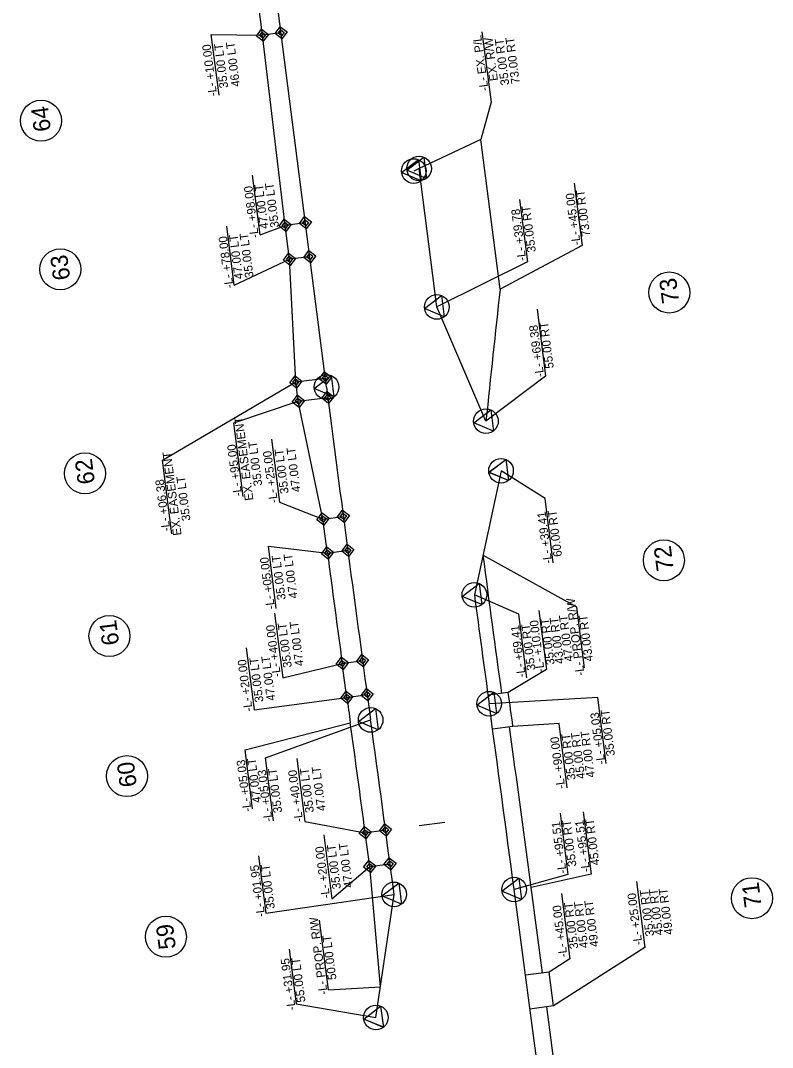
# Model space of a CAD drawing. Extents: x 2368169 to 2369183, y 801414 to 808542.
# Drawn here: x 2368302 to 2368742, y 806520 to 807120 of the extents above; entities that cross this region are included whole.
import ezdxf

# ---------------------------------------------------------------- set-up
doc = ezdxf.new("R2010")
doc.units = 0
for name, color, linetype in [('Prop Easement Construction', 7, 'Continuous'), ('Prop Easement Construction Station Offsets', 7, 'Continuous'), ('Prop Easement Permanent Drainage', 7, 'Continuous'), ('Prop Easement Permanent Drainage Station Offsets', 7, 'Continuous'), ('Prop Easement Permanent Drainage Utility', 7, 'Continuous'), ('Prop Easement Permanent Drainage Utility Station Offsets', 7, 'Continuous'), ('Prop Parcel Number CELL', 7, 'Continuous'), ('Prop Parcel Number Text', 7, 'Continuous'), ('Prop ROW Marker CELL', 7, 'Continuous'), ('Prop ROW Permanent Easement CELL', 7, 'Continuous'), ('Prop ROW RW Lines', 7, 'Continuous'), ('Prop ROW Station Offsets', 7, 'Continuous')]:
    doc.layers.add(name, color=color, linetype=linetype)

msp = doc.modelspace()

# ---------------------------------------------------------------- linework, layer by layer
at = {"layer": 'Prop Easement Construction'}
for p, q in [((2368456.82, 807000.63), (2368443.56, 807111.84)), ((2368463.06, 806909.05), (2368459.36, 806980.79)), ((2368478.97, 806828.89), (2368464.55, 806897.76)), ((2368512.61, 806555.37), (2368506.34, 806625.66)), ((2368607.38, 806563.4), (2368600.76, 806613.48)), ((2368629.17, 806398.45), (2368610, 806543.58))]:
    msp.add_line(p, q, dxfattribs=at)
for centre, radius, start, end in [((2390619.79, 809742.63), 22331.72, 187.54847, 187.715583), ((2391111.53, 809808.52), 22737.85, 187.583666, 187.789219), ((2390193.95, 809683.11), 21901.75, 187.763273, 187.802507), ((2347336.87, 803808.82), 21356.05, 7.63287, 7.806987), ((2345971.56, 803623.74), 22825.85, 7.526261, 7.763901)]:
    msp.add_arc(centre, radius, start, end, dxfattribs=at)
at = {"layer": 'Prop Easement Construction Station Offsets'}
for p, q in [((2368433.36, 806693.96), (2368494.98, 806709.75)), ((2368437.76, 806659.5), (2368433.36, 806693.96)), ((2368482.14, 806553.46), (2368476.92, 806594.32)), ((2368482.14, 806553.46), (2368512.61, 806555.37))]:
    msp.add_line(p, q, dxfattribs=at)
for points in [[(2368631.99, 806741.85), (2368627.46, 806777.36), (2368572.56, 806807.72)], [(2368631.34, 806657.64), (2368635.99, 806621.22), (2368600.76, 806613.48)]]:
    msp.add_lwpolyline(points, dxfattribs=at)
at = {"layer": 'Prop Easement Permanent Drainage'}
for p, q in [((2368571.36, 807050.84), (2368535.23, 807033.87)), ((2368582.58, 806963.32), (2368571.36, 807050.84)), ((2368587.43, 806727.42), (2368575.54, 806725.79)), ((2368590.15, 806707.58), (2368578.26, 806705.96)), ((2368611.34, 806563.93), (2368597.46, 806562.09)), ((2368613.96, 806544.1), (2368611.34, 806563.93)), ((2368613.96, 806544.1), (2368600.08, 806542.27))]:
    msp.add_line(p, q, dxfattribs=at)
for centre, radius, start, end in [((2400172.77, 803560.17), 31772.96, 173.851337, 173.99136), ((2345971.56, 803623.74), 22827.85, 7.763901, 7.814153)]:
    msp.add_arc(centre, radius, start, end, dxfattribs=at)
at = {"layer": 'Prop Easement Permanent Drainage Station Offsets'}
for p, q in [((2368662.43, 806616.97), (2368667.38, 806578.25)), ((2368618.58, 806609.82), (2368623.45, 806571.69)), ((2368667.38, 806578.25), (2368613.96, 806544.1)), ((2368623.45, 806571.69), (2368611.34, 806563.93))]:
    msp.add_line(p, q, dxfattribs=at)
for points in [[(2368571.96, 807113.86), (2368577.41, 807072.68), (2368571.36, 807050.84)], [(2368625.97, 807025.32), (2368630.61, 806988.94), (2368582.58, 806963.32)], [(2368605.39, 806775.37), (2368609.8, 806740.83), (2368587.43, 806727.42)], [(2368621.98, 806671.75), (2368617.17, 806709.37), (2368590.15, 806707.58)]]:
    msp.add_lwpolyline(points, dxfattribs=at)
at = {"layer": 'Prop Easement Permanent Drainage Utility'}
for p, q in [((2368443.56, 807111.84), (2368441.02, 807131.68)), ((2368454.47, 807113.24), (2368443.56, 807111.84)), ((2368468.72, 807002.15), (2368456.82, 807000.63)), ((2368459.36, 806980.79), (2368456.82, 807000.63)), ((2368471.26, 806982.32), (2368459.36, 806980.79)), ((2368463.06, 806909.05), (2368480.37, 806911.33)), ((2368464.55, 806897.76), (2368463.06, 806909.05)), ((2368464.55, 806897.76), (2368481.82, 806899.98)), ((2368478.97, 806828.89), (2368490.87, 806830.46)), ((2368481.6, 806809.02), (2368478.97, 806828.89)), ((2368481.6, 806809.02), (2368493.49, 806810.6)), ((2368490.25, 806744.47), (2368502.14, 806746.08)), ((2368492.95, 806724.61), (2368490.25, 806744.47)), ((2368492.95, 806724.61), (2368504.84, 806726.23)), ((2368503.69, 806645.44), (2368515.59, 806647.03)), ((2368535.32, 806649.68), (2368550.28, 806651.69)), ((2368506.34, 806625.66), (2368503.69, 806645.44)), ((2368506.34, 806625.66), (2368518.23, 806627.24))]:
    msp.add_line(p, q, dxfattribs=at)
at = {"layer": 'Prop Easement Permanent Drainage Utility Station Offsets'}
for p, q in [((2368442.16, 806995.03), (2368437.7, 807029.94)), ((2368427.04, 806965.62), (2368422.64, 807000.07)), ((2368442.16, 806995.03), (2368456.82, 807000.63)), ((2368427.04, 806965.62), (2368459.36, 806980.79)), ((2368384.98, 806863.31), (2368463.06, 806909.05)), ((2368426.73, 806885.17), (2368464.55, 806897.76)), ((2368432.24, 806842.02), (2368426.73, 806885.17)), ((2368390.49, 806820.16), (2368384.98, 806863.31)), ((2368463.6, 806688.93), (2368468.32, 806652.01)), ((2368468.32, 806652.01), (2368503.69, 806645.44))]:
    msp.add_line(p, q, dxfattribs=at)
for points in [[(2368418.15, 807076.8), (2368413.61, 807112.33), (2368443.56, 807111.84)], [(2368448.86, 806875.53), (2368453.55, 806838.79), (2368478.97, 806828.89)], [(2368451.67, 806776.56), (2368447.02, 806812.98), (2368481.6, 806809.02)], [(2368450.68, 806773.78), (2368455.5, 806735.99), (2368490.25, 806744.47)], [(2368434.09, 806753.57), (2368438.72, 806717.27), (2368492.95, 806724.61)], [(2368479.44, 806644.24), (2368484.21, 806606.86), (2368506.34, 806625.66)]]:
    msp.add_lwpolyline(points, dxfattribs=at)
at = {"layer": 'Prop Parcel Number CELL'}
for p, q in [((2368313.96, 807061.81), (2368313.96, 807061.81)), ((2368325.25, 806974.96), (2368325.25, 806974.96)), ((2368681.65, 806961.36), (2368681.65, 806961.36)), ((2368339.69, 806855.59), (2368339.69, 806855.59)), ((2368678.48, 806804.78), (2368678.48, 806804.78)), ((2368354.01, 806760.49), (2368354.01, 806760.49)), ((2368364.24, 806678.53), (2368364.24, 806678.53)), ((2368730.05, 806607.14), (2368730.05, 806607.14)), ((2368387.04, 806584.6), (2368387.04, 806584.6))]:
    msp.add_line(p, q, dxfattribs=at)
for centre in [(2368313.96, 807061.81), (2368325.25, 806974.96), (2368681.65, 806961.36), (2368339.69, 806855.59), (2368678.48, 806804.78), (2368354.01, 806760.49), (2368364.24, 806678.53), (2368730.05, 806607.14), (2368387.04, 806584.6)]:
    msp.add_circle(centre, 12, dxfattribs=at)
at = {"layer": 'Prop ROW Marker CELL'}
for p, q in [((2368532.12, 807032.41), (2368532.12, 807032.41)), ((2368532.12, 807032.41), (2368532.12, 807032.41)), ((2368535.23, 807033.87), (2368535.23, 807033.87)), ((2368535.23, 807033.87), (2368535.23, 807033.87)), ((2368545.61, 806952.91), (2368545.61, 806952.91)), ((2368545.61, 806952.91), (2368545.61, 806952.91)), ((2368481.04, 806906.1), (2368481.04, 806906.1)), ((2368481.04, 806906.1), (2368481.04, 806906.1)), ((2368574.36, 806886.11), (2368574.36, 806886.11)), ((2368574.36, 806886.11), (2368574.36, 806886.11)), ((2368583.18, 806857.11), (2368583.18, 806857.11)), ((2368583.18, 806857.11), (2368583.18, 806857.11)), ((2368567.58, 806784.58), (2368567.58, 806784.58)), ((2368567.58, 806784.58), (2368567.58, 806784.58)), ((2368576.22, 806720.88), (2368576.22, 806720.88)), ((2368576.22, 806720.88), (2368576.22, 806720.88)), ((2368506.87, 806711.38), (2368506.87, 806711.38)), ((2368506.87, 806711.38), (2368506.87, 806711.38)), ((2368590.85, 806612.17), (2368590.85, 806612.17)), ((2368590.85, 806612.17), (2368590.85, 806612.17)), ((2368520.61, 806609.37), (2368520.61, 806609.37)), ((2368520.61, 806609.37), (2368520.61, 806609.37)), ((2368509.95, 806537.37), (2368509.95, 806537.37)), ((2368509.95, 806537.37), (2368509.95, 806537.37))]:
    msp.add_line(p, q, dxfattribs=at)
for points in [[(2368536.49, 807026.67), (2368524.98, 807031.49), (2368534.89, 807039.07)], [(2368536.49, 807026.66), (2368524.98, 807031.5), (2368534.9, 807039.06)], [(2368539.59, 807028.12), (2368528.08, 807032.95), (2368538.01, 807040.52)], [(2368539.6, 807028.13), (2368528.09, 807032.95), (2368538, 807040.52)], [(2368549.98, 806947.18), (2368538.47, 806951.99), (2368548.38, 806959.57)], [(2368549.97, 806947.17), (2368538.47, 806952), (2368548.39, 806959.57)], [(2368485.41, 806900.36), (2368473.9, 806905.18), (2368483.81, 806912.76)], [(2368485.4, 806900.36), (2368473.9, 806905.19), (2368483.82, 806912.76)], [(2368578.73, 806880.37), (2368567.22, 806885.19), (2368577.13, 806892.77)], [(2368578.73, 806880.37), (2368567.22, 806885.2), (2368577.14, 806892.77)], [(2368587.55, 806851.37), (2368576.04, 806856.19), (2368585.96, 806863.77)], [(2368587.55, 806851.37), (2368576.04, 806856.2), (2368585.96, 806863.77)], [(2368571.95, 806778.84), (2368560.44, 806783.66), (2368570.35, 806791.23)], [(2368571.94, 806778.83), (2368560.44, 806783.66), (2368570.36, 806791.23)], [(2368580.59, 806715.14), (2368569.08, 806719.96), (2368578.99, 806727.54)], [(2368580.58, 806715.14), (2368569.08, 806719.97), (2368579, 806727.54)], [(2368511.23, 806705.64), (2368499.72, 806710.46), (2368509.64, 806718.04)], [(2368511.23, 806705.63), (2368499.72, 806710.47), (2368509.64, 806718.03)], [(2368595.21, 806606.43), (2368583.7, 806611.25), (2368593.62, 806618.83)], [(2368595.21, 806606.43), (2368583.7, 806611.26), (2368593.62, 806618.83)], [(2368524.97, 806603.63), (2368513.46, 806608.46), (2368523.39, 806616.03)], [(2368524.98, 806603.64), (2368513.47, 806608.45), (2368523.38, 806616.03)], [(2368514.31, 806531.62), (2368502.8, 806536.46), (2368512.73, 806544.02)], [(2368514.32, 806531.63), (2368502.81, 806536.45), (2368512.72, 806544.03)]]:
    msp.add_lwpolyline(points, close=True, dxfattribs=at)
for centre in [(2368532.12, 807032.41), (2368535.23, 807033.87), (2368545.61, 806952.91), (2368481.04, 806906.1), (2368574.36, 806886.11), (2368583.18, 806857.11), (2368567.58, 806784.58), (2368576.22, 806720.88), (2368506.87, 806711.38), (2368520.61, 806609.37), (2368590.85, 806612.17), (2368509.95, 806537.37)]:
    msp.add_circle(centre, 7.2, dxfattribs=at)
at = {"layer": 'Prop ROW Permanent Easement CELL'}
for p, q in [((2368443.56, 807111.84), (2368443.56, 807111.84)), ((2368454.47, 807113.24), (2368454.47, 807113.24)), ((2368468.72, 807002.15), (2368468.72, 807002.15)), ((2368456.82, 807000.63), (2368456.82, 807000.63)), ((2368459.36, 806980.79), (2368459.36, 806980.79)), ((2368471.26, 806982.32), (2368471.26, 806982.32)), ((2368480.37, 806911.33), (2368480.37, 806911.33)), ((2368463.06, 806909.05), (2368463.06, 806909.05)), ((2368481.82, 806899.98), (2368481.82, 806899.98)), ((2368464.55, 806897.76), (2368464.55, 806897.76)), ((2368478.97, 806828.89), (2368478.97, 806828.89)), ((2368490.87, 806830.46), (2368490.87, 806830.46)), ((2368481.6, 806809.02), (2368481.6, 806809.02)), ((2368493.49, 806810.6), (2368493.49, 806810.6)), ((2368490.25, 806744.47), (2368490.25, 806744.47)), ((2368502.14, 806746.08), (2368502.14, 806746.08)), ((2368492.95, 806724.61), (2368492.95, 806724.61)), ((2368504.84, 806726.23), (2368504.84, 806726.23)), ((2368515.59, 806647.03), (2368515.59, 806647.03)), ((2368503.69, 806645.44), (2368503.69, 806645.44)), ((2368506.34, 806625.66), (2368506.34, 806625.66)), ((2368518.23, 806627.24), (2368518.23, 806627.24))]:
    msp.add_line(p, q, dxfattribs=at)
for points in [[(2368444.03, 807108.28), (2368439.99, 807111.37), (2368443.09, 807115.41), (2368447.13, 807112.32)], [(2368454.95, 807109.68), (2368450.9, 807112.77), (2368454, 807116.81), (2368458.04, 807113.72)], [(2368454.71, 807111.46), (2368452.69, 807113.01), (2368454.24, 807115.03), (2368456.26, 807113.48)], [(2368443.8, 807110.06), (2368441.78, 807111.61), (2368443.33, 807113.63), (2368445.35, 807112.08)], [(2368457.29, 806997.06), (2368453.25, 807000.15), (2368456.35, 807004.2), (2368460.39, 807001.1)], [(2368457.05, 806998.84), (2368455.03, 807000.39), (2368456.58, 807002.41), (2368458.6, 807000.86)], [(2368469.19, 806998.59), (2368465.15, 807001.68), (2368468.25, 807005.72), (2368472.29, 807002.63)], [(2368468.96, 807000.37), (2368466.94, 807001.92), (2368468.48, 807003.94), (2368470.5, 807002.39)], [(2368459.83, 806977.22), (2368455.79, 806980.32), (2368458.89, 806984.36), (2368462.93, 806981.26)], [(2368471.74, 806978.75), (2368467.7, 806981.84), (2368470.79, 806985.88), (2368474.83, 806982.79)], [(2368471.5, 806980.53), (2368469.48, 806982.08), (2368471.03, 806984.1), (2368473.05, 806982.55)], [(2368459.6, 806979.01), (2368457.58, 806980.55), (2368459.13, 806982.57), (2368461.15, 806981.03)], [(2368462.61, 806912.62), (2368466.63, 806909.51), (2368463.52, 806905.48), (2368459.49, 806908.6)], [(2368462.83, 806910.84), (2368464.85, 806909.28), (2368463.29, 806907.27), (2368461.28, 806908.83)], [(2368479.91, 806914.9), (2368483.94, 806911.79), (2368480.82, 806907.76), (2368476.8, 806910.87)], [(2368480.14, 806913.11), (2368482.15, 806911.56), (2368480.6, 806909.54), (2368478.58, 806911.1)], [(2368464.09, 806901.33), (2368468.12, 806898.22), (2368465, 806894.19), (2368460.97, 806897.3)], [(2368464.32, 806899.55), (2368466.33, 806897.99), (2368464.77, 806895.98), (2368462.76, 806897.53)], [(2368481.37, 806903.55), (2368485.4, 806900.44), (2368482.28, 806896.41), (2368478.25, 806899.52)], [(2368481.6, 806901.77), (2368483.61, 806900.21), (2368482.05, 806898.2), (2368480.04, 806899.75)], [(2368487.3, 806830), (2368490.41, 806834.03), (2368494.44, 806830.92), (2368491.33, 806826.89)], [(2368475.4, 806828.44), (2368478.52, 806832.46), (2368482.54, 806829.35), (2368479.43, 806825.32)], [(2368477.19, 806828.67), (2368478.74, 806830.68), (2368480.76, 806829.12), (2368479.2, 806827.11)], [(2368489.08, 806830.23), (2368490.64, 806832.24), (2368492.65, 806830.69), (2368491.1, 806828.67)], [(2368478.03, 806808.57), (2368481.14, 806812.6), (2368485.17, 806809.48), (2368482.05, 806805.45)], [(2368479.81, 806808.8), (2368481.37, 806810.81), (2368483.38, 806809.25), (2368481.82, 806807.24)], [(2368489.92, 806810.15), (2368493.04, 806814.17), (2368497.06, 806811.06), (2368493.95, 806807.03)], [(2368491.71, 806810.37), (2368493.26, 806812.39), (2368495.28, 806810.83), (2368493.72, 806808.82)], [(2368498.57, 806745.62), (2368501.68, 806749.65), (2368505.71, 806746.53), (2368502.59, 806742.51)], [(2368486.68, 806744.01), (2368489.79, 806748.04), (2368493.82, 806744.92), (2368490.7, 806740.9)], [(2368488.46, 806744.24), (2368490.02, 806746.25), (2368492.03, 806744.7), (2368490.47, 806742.68)], [(2368500.35, 806745.85), (2368501.91, 806747.86), (2368503.92, 806746.31), (2368502.37, 806744.29)], [(2368489.37, 806724.15), (2368492.49, 806728.18), (2368496.52, 806725.06), (2368493.4, 806721.04)], [(2368491.16, 806724.38), (2368492.72, 806726.39), (2368494.73, 806724.84), (2368493.17, 806722.82)], [(2368501.26, 806725.77), (2368504.38, 806729.8), (2368508.41, 806726.69), (2368505.29, 806722.66)], [(2368503.05, 806726), (2368504.61, 806728.02), (2368506.62, 806726.46), (2368505.06, 806724.44)], [(2368500.12, 806644.98), (2368503.24, 806649.01), (2368507.26, 806645.89), (2368504.15, 806641.87)], [(2368501.91, 806645.21), (2368503.47, 806647.22), (2368505.48, 806645.67), (2368503.92, 806643.65)], [(2368512.02, 806646.58), (2368515.13, 806650.6), (2368519.16, 806647.49), (2368516.04, 806643.46)], [(2368513.8, 806646.81), (2368515.36, 806648.82), (2368517.37, 806647.26), (2368515.82, 806645.25)], [(2368505.88, 806629.23), (2368509.91, 806626.11), (2368506.79, 806622.09), (2368502.77, 806625.2)], [(2368514.66, 806626.78), (2368517.78, 806630.81), (2368521.8, 806627.7), (2368518.69, 806623.67)], [(2368516.45, 806627.01), (2368518.01, 806629.03), (2368520.02, 806627.47), (2368518.46, 806625.45)], [(2368506.11, 806627.44), (2368508.12, 806625.88), (2368506.57, 806623.87), (2368504.55, 806625.43)]]:
    msp.add_lwpolyline(points, close=True, dxfattribs=at)
at = {"layer": 'Prop ROW RW Lines'}
for p, q in [((2368481.04, 806906.1), (2368402.36, 807519.55)), ((2368535.23, 807033.87), (2368532.12, 807032.41)), ((2368545.61, 806952.91), (2368535.23, 807033.87)), ((2368574.36, 806886.11), (2368545.61, 806952.91)), ((2368583.18, 806857.11), (2368567.58, 806784.58)), ((2368614.67, 806431.84), (2368590.85, 806612.17)), ((2368509.95, 806537.37), (2368520.61, 806609.37))]:
    msp.add_line(p, q, dxfattribs=at)
for centre, radius, start, end in [((2391111.53, 809808.52), 22815.85, 187.308437, 187.801711), ((2391111.53, 809808.52), 22745.85, 187.639798, 187.801711), ((2345971.56, 803623.74), 22815.85, 7.526261, 7.801711), ((2345971.56, 803623.74), 22745.85, 7.542448, 7.801711)]:
    msp.add_arc(centre, radius, start, end, dxfattribs=at)
at = {"layer": 'Prop ROW Station Offsets'}
for p, q in [((2368608.92, 806840.95), (2368583.18, 806857.11)), ((2368613.73, 806803.26), (2368608.92, 806840.95)), ((2368639.87, 806724.55), (2368576.22, 806720.88)), ((2368644.81, 806685.91), (2368639.87, 806724.55)), ((2368445.32, 806689.25), (2368506.87, 806711.38)), ((2368450.03, 806652.36), (2368445.32, 806689.25)), ((2368441.2, 806631.97), (2368445.5, 806598.3)), ((2368445.5, 806598.3), (2368520.61, 806609.37))]:
    msp.add_line(p, q, dxfattribs=at)
for points in [[(2368593.99, 807015.78), (2368598.64, 806979.4), (2368545.61, 806952.91)], [(2368604.3, 806951.66), (2368609.3, 806912.51), (2368574.36, 806886.11)], [(2368598.31, 806735.99), (2368593.56, 806773.17), (2368567.58, 806784.58)], [(2368617.71, 806656.87), (2368622.3, 806620.91), (2368590.85, 806612.17)], [(2368459.11, 806577.42), (2368463.21, 806545.3), (2368509.95, 806537.37)]]:
    msp.add_lwpolyline(points, dxfattribs=at)

# ---------------------------------------------------------------- texts
at = {"layer": 'Prop Easement Construction Station Offsets'}
for s, p in [('-L- PROP. R/W', (2368632.04, 806737.56)), ('43.00 RT', (2368637.02, 806745.91)), ('47.00 LT', (2368442.8, 806663.16)), ('-L- +05.03', (2368437.16, 806657.98)), ('-L- +95.51', (2368635.3, 806622.68)), ('45.00 RT', (2368640.84, 806626.66)), ('-L- PROP. R/W', (2368481.68, 806551.01)), ('50.00 LT', (2368486.87, 806559.69))]:
    msp.add_text(s, height=5, rotation=97.27835, dxfattribs=at).set_placement(p)
at = {"layer": 'Prop Easement Permanent Drainage Station Offsets'}
for s, rotation, p in [('-L- EX. P/L', 97.54241, (2368575.87, 807079.54)), ('EX. R/W', 97.54241, (2368581.41, 807085.37)), ('35.00 RT', 97.54241, (2368588.04, 807082.89)), ('73.00 RT', 97.54241, (2368594.24, 807083.71)), ('-L- +45.00', 97.27835, (2368629.75, 806989.38)), ('73.00 RT', 97.27835, (2368635.41, 806994.38)), ('-L- +10.00', 97.27835, (2368608.69, 806739.61)), ('35.00 RT', 97.27835, (2368614.64, 806743.93)), ('43.00 RT', 97.27835, (2368620.03, 806744.46)), ('47.00 RT', 97.27835, (2368625.46, 806745.84)), ('-L- +90.00', 97.27835, (2368620.75, 806671.44)), ('35.00 RT', 97.27835, (2368626.87, 806676.5)), ('45.00 RT', 97.27835, (2368632.47, 806677.21)), ('47.00 RT', 97.27835, (2368638.15, 806678.01)), ('35.00 RT', 97.27835, (2368672.79, 806585.18)), ('45.00 RT', 97.27835, (2368678.1, 806585.74)), ('49.00 RT', 97.27835, (2368683.84, 806586.06)), ('35.00 RT', 97.27835, (2368628.44, 806577.79)), ('45.00 RT', 97.27835, (2368634.25, 806578.26)), ('49.00 RT', 97.27835, (2368640.31, 806578.93)), ('-L- +25.00', 97.27835, (2368665.89, 806580.02)), ('-L- +45.00', 97.27835, (2368622.04, 806572.87))]:
    msp.add_text(s, height=5, rotation=rotation, dxfattribs=at).set_placement(p)
at = {"layer": 'Prop Easement Permanent Drainage Utility Station Offsets'}
for s, p in [('-L- +10.00', (2368417.04, 807076.36)), ('35.00 LT', (2368423.48, 807081.15)), ('46.00 LT', (2368430.43, 807082.04)), ('35.00 LT', (2368453.28, 806999.61)), ('-L- +98.00', (2368441.45, 806993.53)), ('47.00 LT', (2368447.08, 806998.82)), ('47.00 LT', (2368432.22, 806969.45)), ('35.00 LT', (2368438.42, 806970.24)), ('-L- +78.00', (2368426.6, 806964.16)), ('EX. EASEMENT', (2368438.26, 806839.96)), ('-L- +95.00', (2368431.65, 806842.43)), ('35.00 LT', (2368443.47, 806848.51)), ('-L- +25.00', (2368452.57, 806838.61)), ('35.00 LT', (2368458.94, 806844)), ('47.00 LT', (2368465.88, 806844.89)), ('EX. EASEMENT', (2368396.23, 806819.53)), ('-L- +06.38', (2368389.62, 806822)), ('35.00 LT', (2368401.44, 806828.08)), ('-L- +05.00', (2368450.83, 806776.46)), ('35.00 LT', (2368457.2, 806781.85)), ('47.00 LT', (2368464.14, 806782.73)), ('-L- +40.00', (2368454.38, 806736.86)), ('35.00 LT', (2368460.75, 806742.25)), ('47.00 LT', (2368467.7, 806743.14)), ('-L- +20.00', (2368437.79, 806716.65)), ('35.00 LT', (2368444.16, 806722.04)), ('47.00 LT', (2368451.1, 806722.93)), ('35.00 LT', (2368473.68, 806657.4)), ('47.00 LT', (2368480.62, 806658.29)), ('-L- +40.00', (2368467.31, 806652.01)), ('-L- +20.00', (2368483.14, 806607.33)), ('35.00 LT', (2368489.51, 806612.72)), ('47.00 LT', (2368496.46, 806613.6))]:
    msp.add_text(s, height=5, rotation=97.27835, dxfattribs=at).set_placement(p)
at = {"layer": 'Prop Parcel Number Text'}
for s, p in [('64', (2368319.8, 807056.05)), ('63', (2368331.09, 806969.17)), ('73', (2368687.49, 806955.6)), ('62', (2368345.53, 806849.85)), ('72', (2368684.32, 806799.02)), ('61', (2368359.73, 806755.66)), ('60', (2368370.09, 806672.71)), ('71', (2368735.77, 806602.29)), ('59', (2368392.94, 806577.84))]:
    msp.add_text(s, height=10, rotation=97.27835, dxfattribs=at).set_placement(p)
at = {"layer": 'Prop ROW Station Offsets'}
for s, p in [('-L- +39.78', (2368597.92, 806980.16)), ('35.00 RT', (2368603.58, 806985.15)), ('-L- +69.38', (2368608.4, 806912.21)), ('55.00 RT', (2368614.06, 806917.2)), ('-L- +39.41', (2368613.12, 806803.1)), ('60.00 RT', (2368618.91, 806807.12)), ('-L- +69.41', (2368597.59, 806736.63)), ('35.00 RT', (2368603.38, 806740.65)), ('-L- +05.03', (2368644.21, 806685.68)), ('35.00 RT', (2368649.88, 806690.57)), ('35.00 LT', (2368455.07, 806657.32)), ('-L- +05.03', (2368449.43, 806652.14)), ('35.00 RT', (2368627.33, 806625.91)), ('-L- +95.51', (2368621.55, 806621.89)), ('-L- +01.95', (2368445.1, 806596.47)), ('35.00 LT', (2368450.82, 806601.07)), ('-L- +31.95', (2368463.01, 806541.92)), ('55.00 LT', (2368468.73, 806546.51))]:
    msp.add_text(s, height=5, rotation=97.27835, dxfattribs=at).set_placement(p)

doc.saveas('drawing.dxf')
